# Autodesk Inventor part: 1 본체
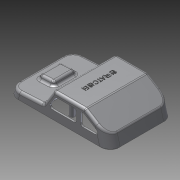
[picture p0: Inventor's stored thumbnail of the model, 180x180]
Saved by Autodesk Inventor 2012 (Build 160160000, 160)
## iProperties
Created: 2015-05
Part Number: 1 본체
Material: Default
Document SubType Name: Modeling
Designer: Owner
Density: 1 g/cm^3
Author: Owner
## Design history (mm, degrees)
sketch "스케치1"
  geometry: L1 (0, 0)-(122, 0); L2 (2.174, 9.114)-(42, 11.201); L3 (42, 11.201)-(54.372, 31); L4 (0, 0)-(0, 9); L5 (2.174, 9.114)-(0, 9); L6 (54.372, 31)-(92, 31); L7 (92, 31)-(118.378, 14.517); L8 (0, 0)-(0, 1); L9 (2.174, 9.114)-(0, 1); L10 (118.378, 14.517)-(122, 1); L11 (122, 1)-(122, 0)
  constraints: 22 end point, 3 point on line, 2 perpendicular, 1 collinear, 1 horizontal, 1 parallel
  dimensions: "d0" = 122 distance of L1.start L1.end; "d6" = 125 deg angle of L3 L2; "d8" = 42 horizontal distance of L2.end L1.start; "d10" = 3 deg angle of L1 L2; "d15" = 9 distance of L1.start L4.end; "d24" = 31 distance between parallel lines of L1 L6; "d26" = 30 horizontal distance of L1.end L6.end; "d52" = 1 distance of L1.start L8.end; "d53" = 105 deg angle of L1 L9; "d54" = 1 distance of L10.end L1.end; "d56" = 105 deg angle of L1 L10
extrude "돌출1" new body sketch "스케치1" stored distance "d12" = 76; taper "d13" = 0 deg
fillet "모깎기1" dims "d14" = 12
sketch "스케치3"
  geometry: L1 (92, 31)-(118.378, 14.517) reference; L2 (54.372, 31)-(92, 31) reference; L3 (42, 11.201)-(54.372, 31) reference; L4 (122, 0)-(0, 0) reference; L5 (47.77, 11)-(57.143, 26); L6 (90.566, 26)-(114.571, 11); L7 (81.77, 26)-(81.77, 11); L8 (86.571, 11)-(86.571, 26); L9 (57.143, 26)-(81.77, 26); L10 (86.571, 26)-(90.566, 26); L11 (114.571, 11)-(86.571, 11); L12 (81.77, 11)-(47.77, 11); 3 further points
  constraints: 16 end point, 9 parallel, 2 collinear, 2 perpendicular
  dimensions: "d28" = 34 distance of L7.end L5.start; "d29" = 28 distance of L6.end L8.start; "d30" = 5 distance between parallel lines of L5 L3; "d32" = 5 distance between parallel lines of L1 L6; "d33" = 5 distance between parallel lines of L9 L2; "d34" = 15 distance between parallel lines of L12 L9
sketch "스케치4"
  geometry: L1 (11, 9.576)-(12.556, 14.665); L2 (12.556, 14.665)-(28.921, 15.523); L3 (28.921, 15.523)-(31, 10.625); L4 (42, 11.201)-(14.774, 9.774) reference; L5 (2.174, 9.114)-(14.774, 9.774) reference; 1 further point
  constraints: 6 end point, 2 point on line
  dimensions: "d41" = 20 horizontal distance of L3.end L1.start; "d42" = 11 horizontal distance of L1.start point (0, 0); "d58" = 70 deg angle of L5 L1; "d59" = 70 deg angle of L4 L3; "d60" = 5 distance between parallel lines of L4 L2
extrude "돌출3" join sketch "스케치4" stored distance "d43" = 26; taper "d44" = 0 deg
fillet "모깎기5" dims "d145" = 3
fillet "모깎기4" dims "d49" = 3
feature "쉘3" dims "d45" = 2
extrude "돌출4" cut sketch "스케치3" stored distance "d46" = 26; taper "d47" = 0 deg
fillet "모깎기3" dims "d48" = 3
sketch "스케치6"
  geometry: L1 (109.845, -66.479)-(109.845, -9.521) reference; L2 (97.689, 0)-(0, 0) reference; L3 (-12.155, -9.521)-(-12.155, -66.479) reference; L4 (0, -76)-(97.689, -76) reference; L5 (0, -1)-(97.689, -1); L6 (108.845, -9.632)-(108.845, -66.368); L7 (97.689, -75)-(0, -75); L8 (-11.155, -66.368)-(-11.155, -9.632); 5 further points; 4 other entities
  constraints: 8 end point, 7 parallel, 16 other
  dimensions: "d67" = 1 distance between parallel lines of L5 L2
extrude "돌출6" cut sketch "스케치6" distance "d68" = 1; taper "d69" = 0 deg
sketch "스케치7"
  geometry: L1 (-12.155, -64)-(-12.155, -12) reference; L2 (0.268, 0)-(97.421, 0) reference; L3 (0, -75)-(97.689, -75) reference; L4 (48.845, 0)-(48.845, -75); C1 r 3 at (8.845, -38); C2 r 3 at (88.845, -38); C3 r 3 at (48.845, -60); C4 r 3 at (48.845, -16); 2 further points
  constraints: 4 centre point, 3 equal radius, 3 midpoint, 2 end point, 2 horizontal alignment, 2 point on line
  dimensions: "d72" = 6 diameter of C1; "d73" = 40 distance from line of L4 C1.centre; "d74" = 40 distance from line of L4 C2.centre; "d75" = 22 vertical distance of point (-12.155, -38) C3.centre; "d76" = 22 vertical distance of point (-12.155, -38) C4.centre
extrude "돌출7" join sketch "스케치7" stored distance "d77" = 1; taper "d78" = 0 deg
hole "구멍1" diameter "d97" = 3.242; stored, may be unused: countersink angle "d101" = 90 deg, drill point angle "d103" = 118 deg; dims "d95" = 10, "d96" = 10, "d98" = 9, "d99" = 4, "d100" = 2, "d102" = 11
hole "구멍2" diameter "d106" = 3.242; stored, may be unused: countersink angle "d110" = 90 deg, drill point angle "d112" = 118 deg; dims "d104" = 10, "d105" = 10, "d107" = 9, "d108" = 4, "d109" = 2, "d111" = 11
hole "구멍3" diameter "d115" = 3.242; stored, may be unused: countersink angle "d119" = 90 deg, drill point angle "d121" = 118 deg; dims "d113" = 10, "d114" = 10, "d116" = 9, "d117" = 4, "d118" = 2, "d120" = 11
hole "구멍4" diameter "d124" = 3.242; stored, may be unused: countersink angle "d128" = 90 deg, drill point angle "d130" = 118 deg; dims "d122" = 10, "d123" = 10, "d125" = 9, "d126" = 4, "d127" = 2, "d129" = 11
node "작업 평면1"
sketch "스케치10"
  geometry: L1 (-1, -26)-(-1, -38) reference; L2 (-1, -26)-(-1, 26) reference; A1 r 4 centre (-1, -10) between (-1, -6) and (-1, -14); A2 r 4 centre (-1, -21) between (-1, -17) and (-1, -25); 1 further point
  constraints: 6 point on line, 4 point on circle, 2 centre point
  dimensions: "d132" = 10 vertical distance of point (0, 0) A1.centre; "d133" = 11 distance of A1.centre A2.centre; "d134" = 4 radius of A2; "d135" = 4 radius of A1
extrude "돌출8" join sketch "스케치10" stored distance "d136" = 2; taper "d137" = 0 deg
node "작업 평면2"
sketch "스케치11"
  geometry: L1 (66.628, 66.368)-(66.628, 9.632) reference; 2 further points
  constraints: 1 horizontal alignment, 1 other
  dimensions: "d139" = 50 distance from line of point (16.628, 38) L1
feature "엠보싱1" sketch "스케치11" dims "d0" = 122, "d6" = 125 deg, "d8" = 42, "d10" = 3 deg, "d15" = 9, "d24" = 31, "d26" = 30, "d28" = 34, "d29" = 28, "d30" = 5, "d32" = 5, "d33" = 5, "d34" = 15, "d52" = 1, "d53" = 105 deg, "d54" = 1, "d56" = 105 deg, "d140" = 0.5, "d141" = 0
chamfer "모따기1" distance "d142" = 1; stored, may be unused: second distance "d143" = 2, angle "d144" = 45 deg
fillet "모깎기6" dims "d146" = 3
fillet "모깎기7" dims "d147" = 3
node "솔리드1"
mirror "대칭1"
other parameters: "d131" = -2
